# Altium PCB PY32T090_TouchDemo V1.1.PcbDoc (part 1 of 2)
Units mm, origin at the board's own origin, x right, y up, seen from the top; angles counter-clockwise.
Board outline 86.5 x 140.97 mm, 2 copper layers (Top Layer, Bottom Layer); 152 components, 143 nets, 461 pads, 174 vias.
Unrouted connection lines stored in the file: 2.
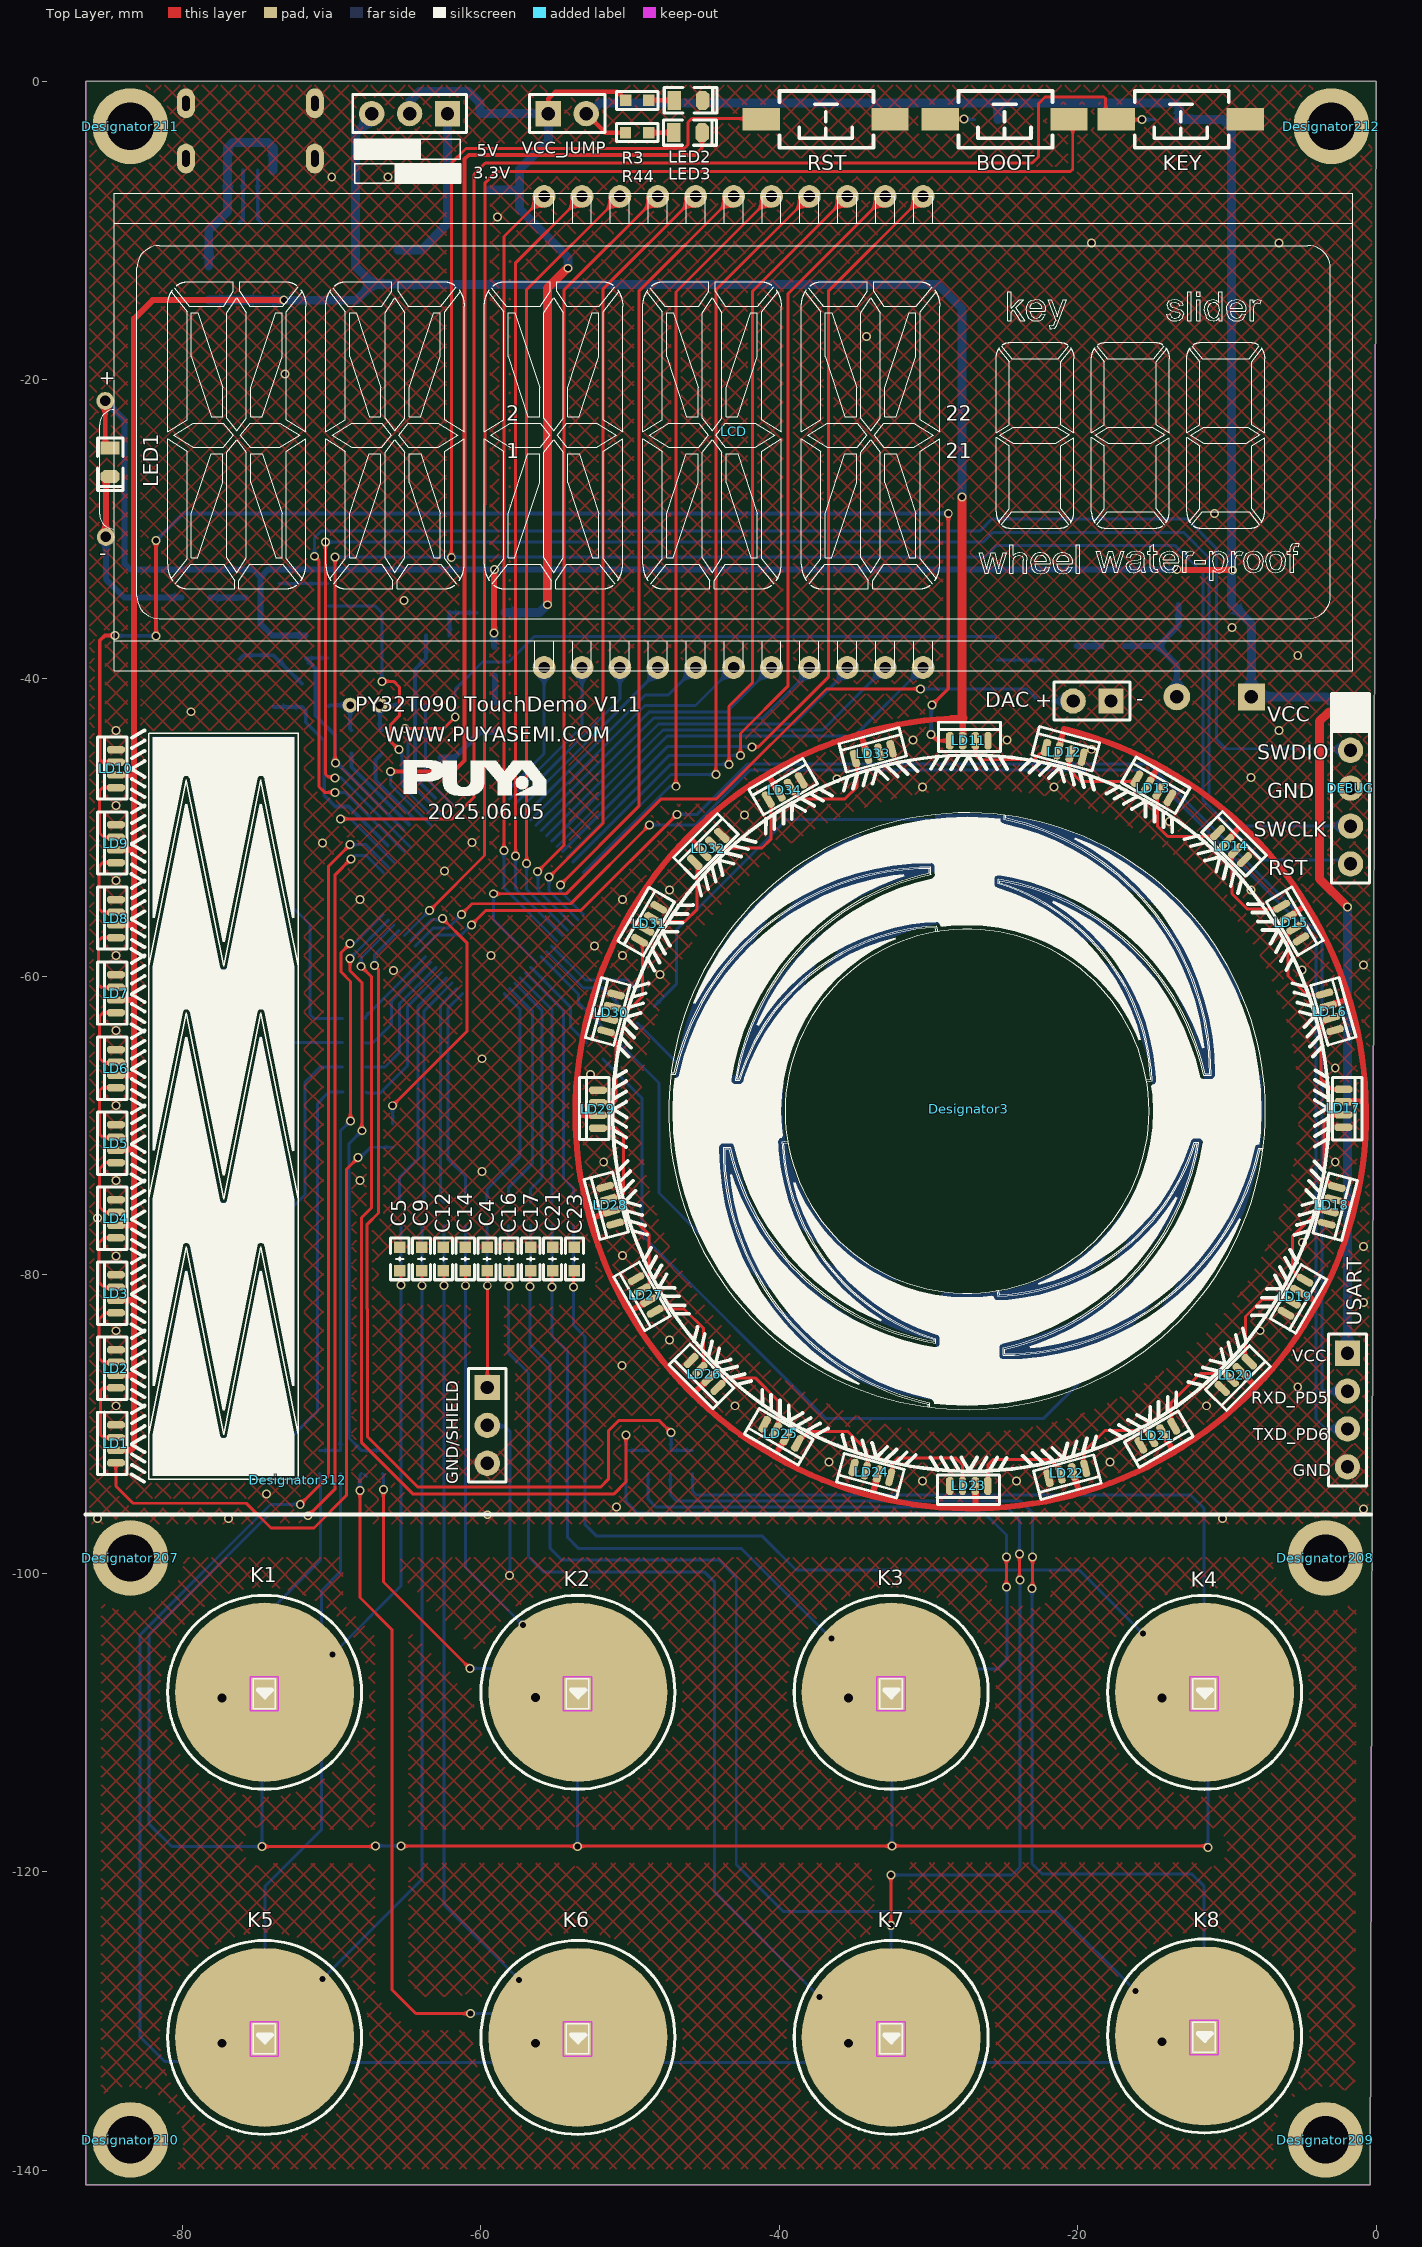
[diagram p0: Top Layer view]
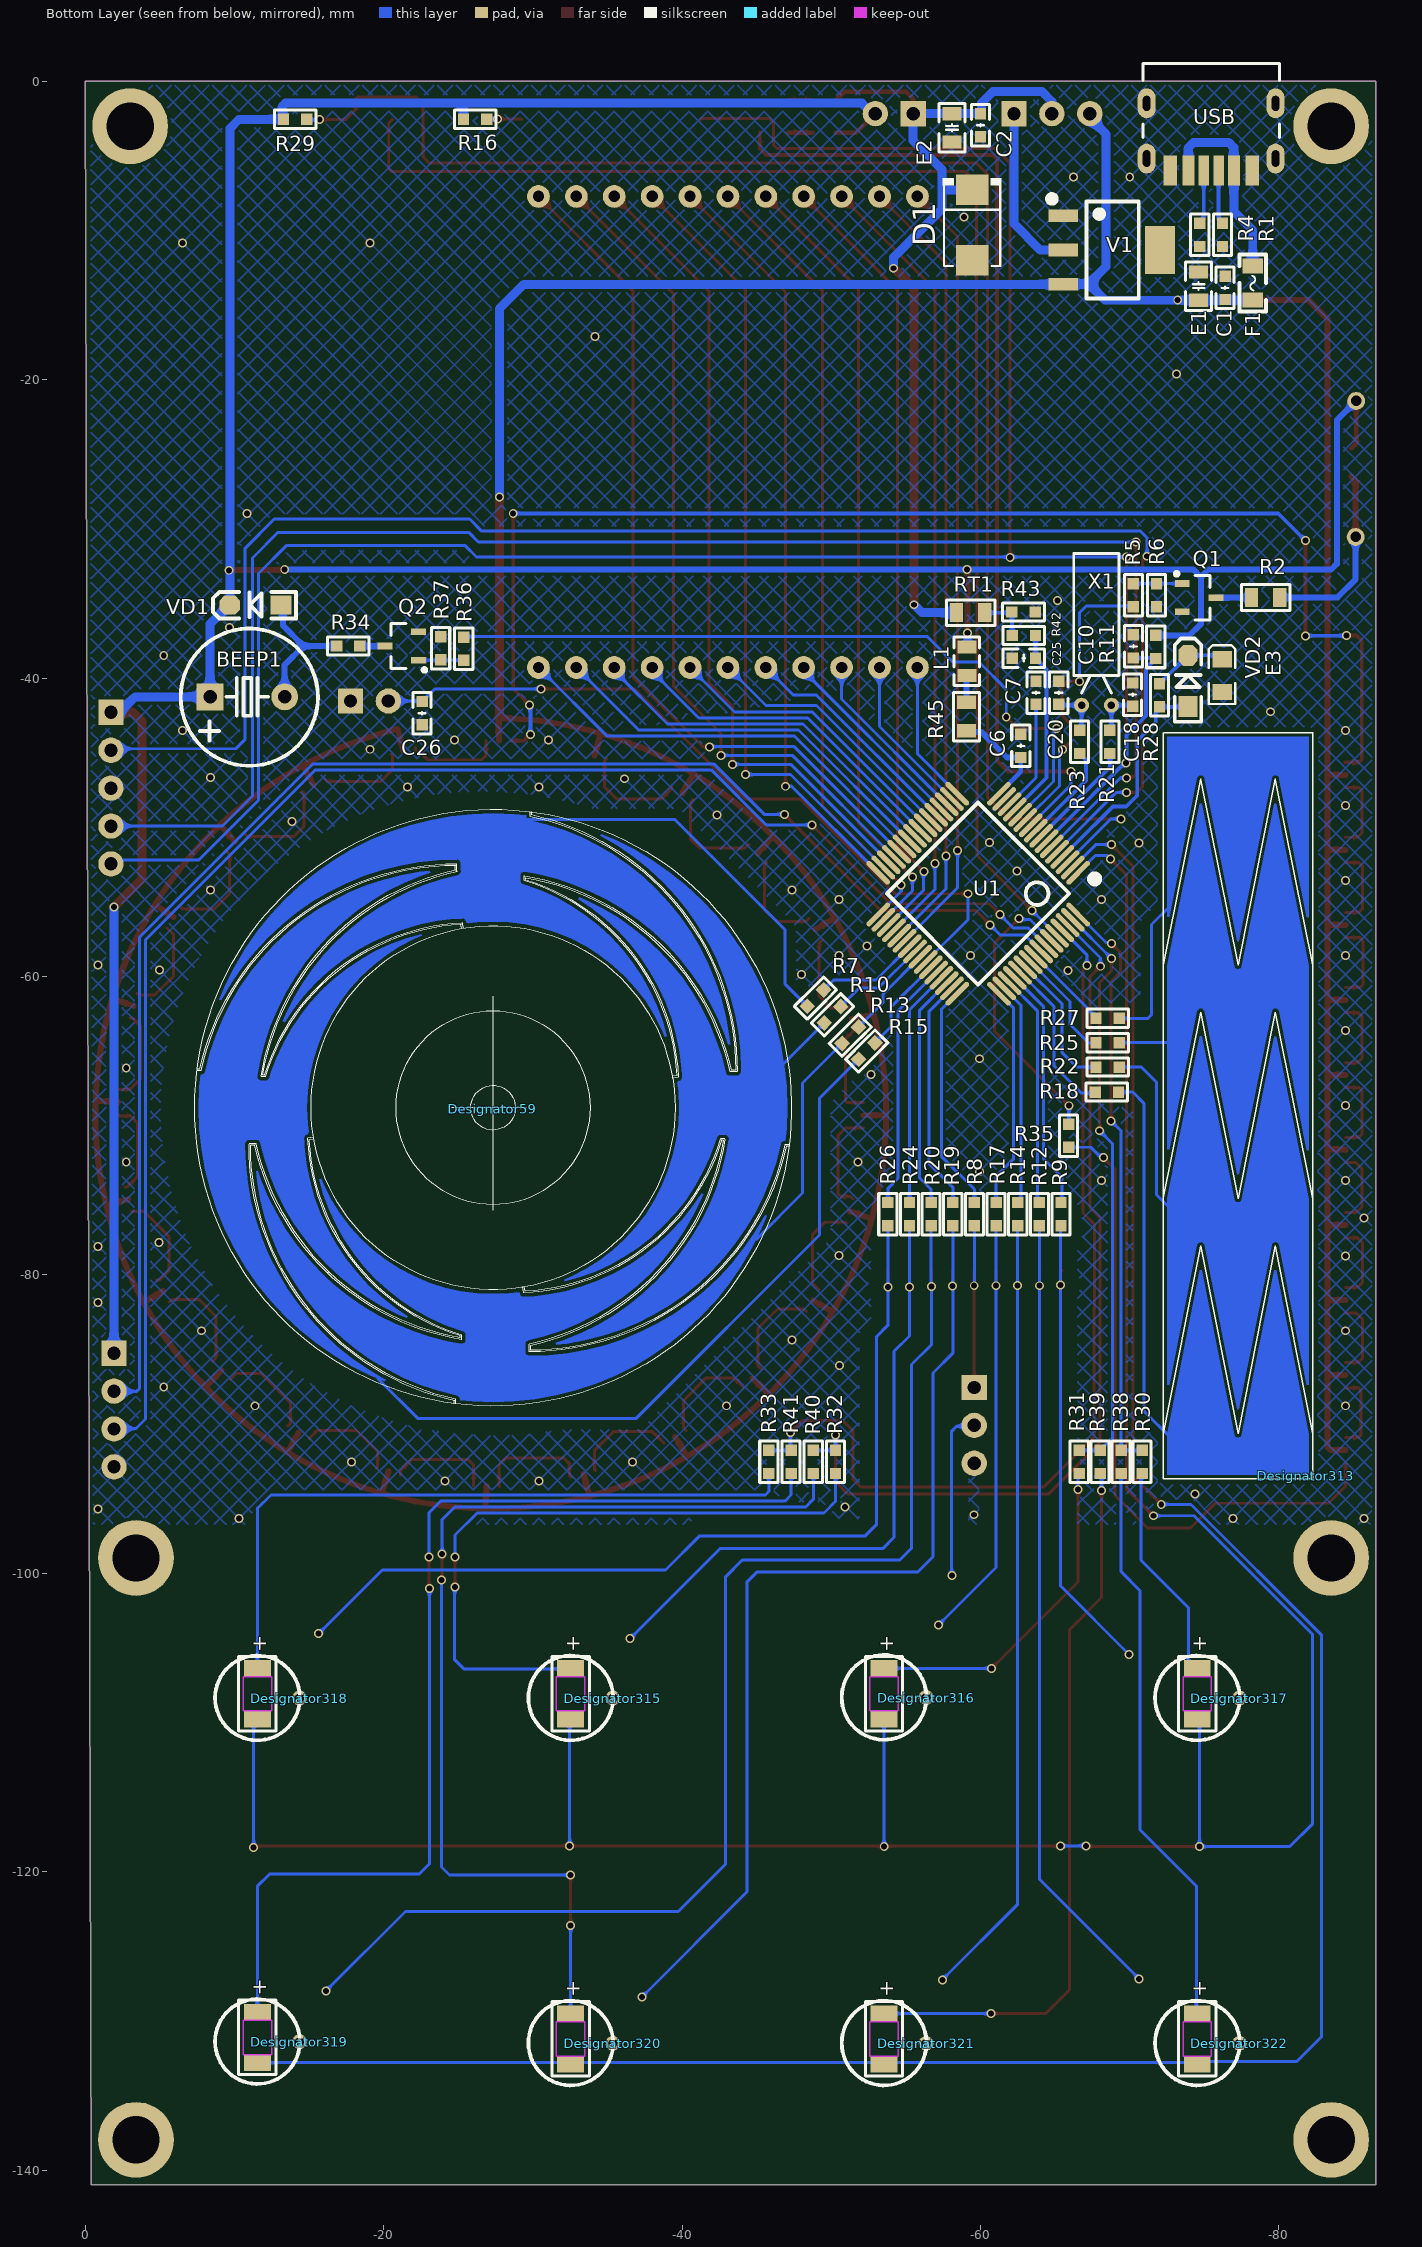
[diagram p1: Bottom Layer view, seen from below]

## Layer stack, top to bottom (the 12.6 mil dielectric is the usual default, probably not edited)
Top Solder: solder mask 0.0102, Solder Resist, Dk 3.5
Top Layer: signal copper 0.0356
Dielectric 1: dielectric 0.32, FR-4, Dk 4.8
Bottom Layer: signal copper 0.0356
Bottom Solder: solder mask 0.0102, Solder Resist, Dk 3.5

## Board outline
-86.5,-140.97 -86.5,0 0,0 -0.394,-140.97

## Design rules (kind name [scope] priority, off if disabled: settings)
Clearance Clearance_17 [All vs InNet('NetC3_2')] p1: gap=0.6 ignorepadtopadclearanceinfootprint=FALSE
Clearance Clearance_16 [All vs InNet('NetC8_2')] p2: gap=0.6 ignorepadtopadclearanceinfootprint=FALSE
Clearance Clearance_15 [All vs InNet('NetC11_2')] p3: gap=0.6 ignorepadtopadclearanceinfootprint=FALSE
Clearance Clearance_14 [All vs InNet('NetC13_2')] p4: gap=0.6 ignorepadtopadclearanceinfootprint=FALSE
Clearance Clearance_13 [All vs InNet('NetC24_2')] p5: gap=0.6 ignorepadtopadclearanceinfootprint=FALSE
Clearance Clearance_12 [All vs InNet('NetC22_2')] p6: gap=0.6 ignorepadtopadclearanceinfootprint=FALSE
Clearance Clearance_11 [All vs InNet('NetC19_2')] p7: gap=0.6 ignorepadtopadclearanceinfootprint=FALSE
Clearance Clearance_10 [All vs InNet('NetC15_2')] p8: gap=0.6 ignorepadtopadclearanceinfootprint=FALSE
Clearance Clearance_9 [All vs InNet('shield_pad')] p9: gap=1 ignorepadtopadclearanceinfootprint=FALSE
Clearance Clearance_18 [All vs InNet('NetC4_2')] p10: gap=1 ignorepadtopadclearanceinfootprint=FALSE
Clearance [All vs InNet('NetC5_2')] p11: gap=1 ignorepadtopadclearanceinfootprint=FALSE
Clearance Clearance_8 [All vs InNet('NetC17_2')] p12: gap=1 ignorepadtopadclearanceinfootprint=FALSE
Clearance Clearance_7 [All vs InNet('NetC14_2')] p13: gap=1 ignorepadtopadclearanceinfootprint=FALSE
Clearance Clearance_6 [All vs InNet('NetC9_2')] p14: gap=1 ignorepadtopadclearanceinfootprint=FALSE
Clearance Clearance_5 [All vs InNet('NetC12_2')] p15: gap=1 ignorepadtopadclearanceinfootprint=FALSE
Clearance Clearance_4 [All vs InNet('NetC21_2')] p16: gap=1 ignorepadtopadclearanceinfootprint=FALSE
Clearance Clearance_3 [All vs InNet('NetC16_2')] p17: gap=1 ignorepadtopadclearanceinfootprint=FALSE
Clearance Clearance_2 [All vs InNet('NetC23_2')] p18: gap=1 ignorepadtopadclearanceinfootprint=FALSE
Clearance Clearance_1 [All] p19: gap=0.2 ignorepadtopadclearanceinfootprint=FALSE
PlaneConnect [All] p1: planeconnectstyle=Direct reliefexpansion=0.508 reliefentries=4 reliefconductorwidth=0.254 reliefairgap=0.254
PolygonConnect [All] p1: connectstyle=Direct reliefconductorwidth=0.254 reliefentries=4 polygonreliefangle="90 Angle" airgapwidth=0.254
RoutingVias [All] p1: holewidth=0.711 width=1.27 viastyle="Through Hole" minholewidth=0.711 minwidth=1.27 maxholewidth=0.711 maxwidth=1.27
SolderMaskExpansion [All] p1: expansion=0.102 istentingtop=FALSE
Width [All] p1: maxlimit=1 minlimit=0.2 preferedwidth=0.254
29 further rules are at their usual default settings.

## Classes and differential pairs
component class PY32T092_TK_TEST: 5V BOOT C1 C2 C4 C5 C6 C7 C9 C10 C12 C14 C16 C17 C18 C20 C21 C23 C25 C26 DAC DEBUG E1 E2 E3 F1 K1 K2 K3 K4 K5 K6 K7 K8 KEY LCD LED1 LED2 LED3 Q1 R1 R2 R3 R4 R5 R6 R7 R8 R9 R10 R11 R12 R13 R14 R15 R16 R17 R18 R19 R20 R21 R22 R23 R24 R25 R26 R27 R28 R29 R42 R43 R44 RST RT1 U1 USART USB V1 VCC_JUMP VD2 X1
component class "PY32T092_Demo LED": BEEP1 LD1 LD2 LD3 LD4 LD5 LD6 LD7 LD8 LD9 LD10 LD11 LD12 LD13 LD14 LD15 LD16 LD17 LD18 LD19 LD20 LD21 LD22 LD23 LD24 LD25 LD26 LD27 LD28 LD29 LD30 LD31 LD32 LD33 LD34 Q2 R30 R31 R32 R33 R34 R35 R36 R37 R38 R39 R40 R41 VD1

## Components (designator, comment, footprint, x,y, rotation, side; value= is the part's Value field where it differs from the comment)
5V "HDR-1X3" HDR2.54-LI-3P -64.783,-2.159 r180 top (schematic designator JUMP)
BEEP1 "DC5V" "BEEP 5x9x5.5" -10.859,-41.25 r270 bottom
BOOT "6x6x5" "TSW SMD-3*6*5" -24.905,-2.54 r180 top
C1 "104" "C 0603_L" -76.391,-13.843 r270 bottom
C2 "104" "C 0603_L" -59.995,-2.936 r90 bottom
C4 "5pf" "C 0603_L" -59.589,-78.928 r270 top
C5 "5pf" "C 0603_L" -65.443,-78.928 r270 top
C6 "104" "C 0603_L" -62.7,-44.539 r270 bottom
C7 "2.2NF" "C 0603_L" -63.716,-40.97 r270 bottom
C9 "5pf" "C 0603_L" -63.98,-78.928 r270 top
C10 "104" "C 0603_L" -70.244,-37.871 r270 bottom
C12 "5pf" "C 0603_L" -62.516,-78.928 r270 top
C14 "5pf" "C 0603_L" -61.052,-78.928 r270 top
C16 "5pf" "C 0603_L" -58.125,-78.928 r270 top
C17 "5pf" "C 0603_L" -56.661,-78.928 r270 top
C18 "20PF" "C 0603_L" -70.193,-41.097 r270 bottom
C20 "20PF" "C 0603_L" -65.24,-40.97 r90 bottom
C21 "5pf" "C 0603_L" -55.198,-78.928 r270 top
C23 "5pf" "C 0603_L" -53.734,-78.928 r270 top
C25 "104" "C 0603_L" -62.903,-38.659 r180 bottom
C26 "104" "C 0603_L" -22.568,-42.342 r90 bottom
D1 "SMBJ5.0A" SMB_L4.6-W3.6-LS5.3-RD -59.436,-9.625 r270 bottom
DAC "HDR-1X2" HDR2.54-LI-2P -19.038,-41.529 r180 top (schematic designator DAC_OUT)
DEBUG "ISP" ISP_DIP_2.54_5P -1.715,-42.291 r270 top
Designator3 "Comment" "circular ring_top" -27.293,-68.859 r0 top locked
Designator59 "Comment" PAD_Wheel -27.293,-68.859 r90 bottom locked
Designator207 "Comment" "M3 125X200"#1 -78.5,-102.759 r0 top
Designator208 "Comment" "M3 125X200"#2 1.027,-103.318 r0 top
Designator209 "Comment" "M3 125X200"#3 1.129,-140.554 r0 top
Designator210 "Comment" "M3 125X200"#4 -78.78,-140.173 r0 top
Designator211 "Comment" "M3 125X200"#5 -79.008,-6.01 r0 top
Designator212 "Comment" "M3 125X200"#6 1.002,-6.01 r0 top
Designator312 "Comment" T092_WHEEL_TOP -72.276,-93.726 r90 top
Designator313 "Comment" T092_Wheel -81.801,-93.472 r90 bottom
Designator315 "Comment" TP -32.523,-108.347 r180 bottom
Designator316 "Comment" TP -53.524,-108.309 r180 bottom
Designator317 "Comment" TP -74.523,-108.347 r180 bottom
Designator318 "Comment" TP -11.523,-108.347 r180 bottom
Designator319 "Comment" TP -11.523,-131.377 r180 bottom
Designator320 "Comment" TP -32.523,-131.478 r180 bottom
Designator321 "Comment" TP -53.523,-131.478 r180 bottom
Designator322 "Comment" TP -74.523,-131.478 r180 bottom
E1 "10uF/10V" "C 0805_L" -74.613,-13.716 r90 bottom
E2 "10uF/10V" "C 0805_L" -58.09,-3.109 r270 bottom
E3 "220uF/10V" "CD S(2012)" -76.188,-39.827 r270 bottom
F1 "500ma" "FU 0805" -78.245,-13.513 r270 bottom
GND/SHIELD "HDR-1X3" HDR2.54-LI-3P -59.576,-90.081 r270 top
K1 "Comment" T-LED -74.5,-107.97 r90 top (schematic designator K0)
K2 "Comment" T-LED -53.5,-107.97 r90 top (schematic designator K5)
K3 "Comment" T-LED -32.5,-107.97 r90 top (schematic designator K6)
K4 "Comment" T-LED -11.5,-107.97 r90 top (schematic designator K2)
K5 "Comment" T-LED -74.5,-131.101 r90 top (schematic designator K7)
K6 "Comment" T-LED -53.5,-131.101 r90 top (schematic designator K8)
K7 "Comment" T-LED -32.5,-131.101 r90 top (schematic designator K3)
K8 "Comment" T-LED -11.5,-131 r90 top (schematic designator K4)
KEY "6x6x5" "TSW SMD-3*6*5" -13.094,-2.54 r180 top (schematic designator KEY1)
L1 "1uH" "L 0805_L" -59.08,-38.862 r90 bottom
LCD "PY_LCD" PY-LCD -43.066,-23.495 r0 top locked
LD1 "LED1" LED_WS -84.489,-91.298 r90 top
LD2 "LED1" LED_WS -84.489,-86.269 r90 top
LD3 "LED1" LED_WS -84.489,-81.24 r90 top
LD4 "LED1" LED_WS -84.489,-76.211 r90 top
LD5 "LED1" LED_WS -84.489,-71.182 r90 top
LD6 "LED1" LED_WS -84.489,-66.153 r90 top
LD7 "LED1" LED_WS -84.489,-61.124 r90 top
LD8 "LED1" LED_WS -84.489,-56.095 r90 top
LD9 "LED1" LED_WS -84.489,-51.066 r90 top
LD10 "LED1" LED_WS -84.489,-46.037 r90 top
LD11 "LED1" LED_WS -27.267,-44.171 r0 top
LD12 "LED1" LED_WS -20.866,-44.958 r345 top
LD13 "LED1" LED_WS -14.897,-47.371 r330 top
LD14 "LED1" LED_WS -9.69,-51.257 r315.12 top
LD15 "LED1" LED_WS -5.652,-56.388 r300.49 top
LD16 "LED1" LED_WS -3.086,-62.382 r286 top
LD17 "LED1" LED_WS -2.176,-68.849 r270 top
LD18 "LED1" LED_WS -2.959,-75.362 r255 top
LD19 "LED1" LED_WS -5.398,-81.483 r240 top
LD20 "LED1" LED_WS -9.411,-86.741 r225 top
LD21 "LED1" LED_WS -14.669,-90.805 r210 top
LD22 "LED1" LED_WS -20.739,-93.32 r195 top
LD23 "LED1" LED_WS -27.318,-94.158 r180 top
LD24 "LED1" LED_WS -33.82,-93.243 r165 top
LD25 "LED1" LED_WS -39.916,-90.653 r150 top
LD26 "LED1" LED_WS -45.047,-86.639 r135 top
LD27 "LED1" LED_WS -48.996,-81.337 r120 top
LD28 "LED1" LED_WS -51.372,-75.311 r105 top
LD29 "LED1" LED_WS -52.185,-68.859 r90 top
LD30 "LED1" LED_WS -51.296,-62.408 r75 top
LD31 "LED1" LED_WS -48.73,-56.439 r60 top
LD32 "LED1" LED_WS -44.768,-51.41 r45 top
LD33 "LED1" LED_WS -33.693,-45.034 r15 top
LD34 "LED1" LED_WS -39.637,-47.473 r30 top
LED1 "白色" "LED 0805G" -84.849,-25.527 r270 top
LED2 "红色" "LED 0805W" -46.089,-1.27 r0 top
LED3 "红色" "LED 0805W" -46.124,-3.429 r0 top
Q1 "SS8050" SOT23-3L -74.664,-34.605 r270 bottom
Q2 "SS8050" SOT23-3L -21.197,-37.846 r90 bottom
R1 "5.1K" "R 0603_L" -76.213,-10.287 r90 bottom
R2 "10R" "R 0805_L" -79.109,-34.595 r180 bottom
R3 "1K" "R 0603_L" -49.518,-1.27 r180 top
R4 "5.1K" "R 0603_L" -74.689,-10.287 r90 bottom
R5 "1K" "R 0603_L" -70.244,-34.442 r270 bottom
R6 "10K" "R 0603_L" -71.793,-34.442 r90 bottom
R7 "4.3K" "R 0603_L" -48.933,-61.443 r315 bottom
R8 "4.3K" "R 0603_L" -59.589,-75.921 r270 bottom
R9 "4.3K" "R 0603_L" -65.393,-75.921 r270 bottom
R10 "4.3K" "R 0603_L" -50.076,-62.56 r315 bottom
R11 "10K" "R 0603_L" -71.743,-37.907 r90 bottom
R12 "4.3K" "R 0603_L" -63.942,-75.921 r270 bottom
R13 "4.3K" "R 0603_L" -51.27,-63.932 r315 bottom
R14 "4.3K" "R 0603_L" -62.491,-75.921 r270 bottom
R15 "4.3K" "R 0603_L" -52.372,-64.989 r315 bottom
R16 "1K" "R 0603_L" -26.124,-2.54 r0 bottom value=10K
R17 "4.3K" "R 0603_L" -61.04,-75.921 r270 bottom
R18 "4.3K" "R 0603_L" -68.466,-67.742 r180 bottom
R19 "4.3K" "R 0603_L" -58.138,-75.921 r270 bottom
R20 "4.3K" "R 0603_L" -56.687,-75.921 r270 bottom
R21 "0R" "R 0603_L" -68.669,-44.272 r90 bottom
R22 "4.3K" "R 0603_L" -68.517,-66.065 r180 bottom
R23 "0R" "R 0603_L" -66.637,-44.272 r90 bottom
R24 "4.3K" "R 0603_L" -55.236,-75.921 r270 bottom
R25 "4.3K" "R 0603_L" -68.517,-64.431 r180 bottom
R26 "4.3K" "R 0603_L" -53.785,-75.921 r270 bottom
R27 "4.3K" "R 0603_L" -68.517,-62.797 r180 bottom
R28 "1M" "R 0603_L" -71.997,-41.148 r90 bottom value=10K
R29 "10K" "R 0603_L" -14.059,-2.54 r0 bottom
R30 "510R" "R 0603_L" -70.828,-92.532 r270 bottom
R31 "510R" "R 0603_L" -66.612,-92.532 r270 bottom
R32 "510R" "R 0603_L" -50.28,-92.532 r270 bottom
R33 "510R" "R 0603_L" -45.809,-92.532 r270 bottom
R34 "200R" "R 0603_L" -17.615,-37.846 r0 bottom
R35 "510R" "R 0603_L" -65.901,-70.663 r270 bottom
R36 "1K" "R 0603_L" -25.362,-38.024 r90 bottom
R37 "10K" "R 0603_L" -23.813,-37.998 r270 bottom
R38 "510R" "R 0603_L" -69.423,-92.532 r270 bottom
R39 "510R" "R 0603_L" -68.017,-92.532 r270 bottom
R40 "510R" "R 0603_L" -48.789,-92.532 r270 bottom
R41 "510R" "R 0603_L" -47.299,-92.532 r270 bottom
R42 "1K" "R 0603_L" -62.903,-37.135 r180 bottom
R43 "10K" "R 0603_L" -62.878,-35.56 r180 bottom
R44 "1K" "R 0603_L" -49.533,-3.429 r180 top
R45 "10Ω" "R 0805_L" -59.055,-42.57 r270 bottom
RST "6x6x5" "TSW SMD-3*6*5" -36.894,-2.54 r180 top (schematic designator RST1)
RT1 "10K" "R 0805_L" -59.337,-35.611 r180 bottom
U1 "PY32T092" "LQFP64 10x10_M" -59.836,-54.441 r45 bottom
USART "ISP" HDR2.54-Y-LI-4P -1.918,-89.052 r270 top
USB "USB-C" USB-C/S_C -75.455,1.081 r0 bottom (schematic designator USB_POWER1)
V1 "AMS1117-3V3" SOT223_N -68.847,-11.303 r270 bottom
VCC_JUMP "HDR-1X2" HDR2.54-LI-2P -54.217,-2.159 r0 top (schematic designator VCC_JUMP1)
VD1 "A7" SOD-123 -11.392,-35.103 r0 bottom
VD2 "A7" SOD-123 -73.902,-40.183 r90 bottom
X1 "32.768KHZ" OSC-3x8-WI-A -67.771,-41.808 r180 bottom

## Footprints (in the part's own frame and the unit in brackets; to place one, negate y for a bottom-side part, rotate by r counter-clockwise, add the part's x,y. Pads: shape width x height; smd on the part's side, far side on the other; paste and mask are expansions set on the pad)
"BEEP 5x9x5.5" [mm] "5*9*5.5mm(脚距,直径,高度)"
  rect 1.8x1.8 hole 0.9: 1(0,-2.5)
  round 1.8 hole 0.9: 2(0,2.5)
  silkscreen extent -4.57,-4.47 4.62,4.73, body extent -4.5,-4.5 4.5,4.5, height 5.45
"C 0603_L" [mil] "无极性贴片电容"
  rect 30x30 smd: 1(-30.59,0) 2(30.59,0)
  silkscreen extent -55,-24 55,24, body extent -31,-16 31,16, height 32
"C 0805_L" [mil] "无极性贴片电容"
  rect 35x50 smd: 1(-37.4,0) 2(37.4,0)
  silkscreen extent -64,-34 64,34, body extent -39,-24 39,24, height 20
"CD S(2012)" [mm] "长2.0mm，宽1.25mm，厚1.2mm"
  rect 1.1x1.3 smd: 1(-1.1,0) 2(1.1,0)
  silkscreen extent -2.03,-0.89 1.91,0.89, body extent -1,-0.6 1,0.6, height 1.2
"circular ring_top" [mm]
  silkscreen extent -20.12,-20.16 19.87,19.84
"FU 0805" [mil] "贴片保险丝"
  rect 40x55 smd: 1(-45,0) 2(45,0)
  silkscreen extent -75,-35 75,35, body extent -39,-24 39,24, height 20
HDR2.54-LI-2P [mm] "排针，2脚"
  rect 1.7x1.7 hole 0.9: 1(-1.27,0)
  round 1.7 hole 0.9: 2(1.27,0)
  silkscreen extent -2.54,-1.27 2.54,1.27, body extent -2.54,-1.27 2.54,1.27, height 8.5
HDR2.54-LI-3P [mm] "排针，3脚"
  rect 1.7x1.7 hole 0.9: 1(-2.54,0)
  round 1.7 hole 0.9: 2(0,0) 3(2.54,0)
  silkscreen extent -3.81,-1.27 3.81,1.27, body extent -3.81,-1.27 3.81,1.27, height 8.5
HDR2.54-Y-LI-4P [mm] "圆孔排母，4脚"
  rect 1.7x1.7 hole 0.9: 1(-3.81,0)
  round 1.7 hole 0.9: 2(-1.27,0) 3(1.27,0) 4(3.81,0)
  silkscreen extent -5.08,-1.27 5.08,1.27, body extent -5.08,-1.27 5.08,1.27, height 4.31
ISP_DIP_2.54_5P [mm] "5P 下载端口"
  rect 1.7x1.7 hole 0.9: 1(0,0)
  round 1.7 hole 0.9: 2(2.54,0) 3(5.08,0) 4(7.62,0) 5(10.16,0)
  silkscreen extent -1.27,-1.27 11.43,1.27
"L 0805_L" [mil] "小功率贴片电感"
  rect 35x50 smd: 1(-37.4,0) 2(37.4,0)
  silkscreen extent -64,-34 64,34, body extent -39,-24 39,24, height 35
"LED 0805G" [mil] "绿色0805LED"
  rect 35x50 smd: 1(-37.4,0)
  oct 35x50 smd: 2(37.4,0)
  silkscreen extent -64,-33 75,33, body extent -39,-25 39,25, height 32
"LED 0805W" [mm] "白色0805LED"
  rect 0.889x1.27 smd: 1(-0.95,0)
  oct 0.889x1.27 smd: 2(0.95,0)
  silkscreen extent -1.62,-0.85 1.9,0.85, body extent -1,-0.63 1,0.63, height 0.8
LED_WS [mm]
  oct 0.5x1.2 smd: 1(-1.295,-0.021) 2(-0.445,-0.021) 3(0.405,-0.021) 4(1.255,-0.021)
  silkscreen extent -2.57,-1.94 2.54,1.22
"LQFP64 10x10_M" [mm] "64脚，体宽10x10mm，脚距0.5mm"
  oval 0.35x2.1 smd: 1(-3.75,-5.727) 2(-3.25,-5.727) 3(-2.75,-5.727) 4(-2.25,-5.727) 5(-1.75,-5.727) 6(-1.25,-5.727) 7(-0.75,-5.727) 8(-0.25,-5.727) 9(0.25,-5.727) 10(0.75,-5.727) 11(1.25,-5.727) 12(1.75,-5.727) 13(2.25,-5.727) 14(2.75,-5.727) 15(3.25,-5.727) 16(3.75,-5.727) 33(3.75,5.727) 34(3.25,5.727) 35(2.75,5.727) 36(2.25,5.727) 37(1.75,5.727) 38(1.25,5.727) 39(0.75,5.727) 40(0.25,5.727) 41(-0.25,5.727) 42(-0.75,5.727) 43(-1.25,5.727) 44(-1.75,5.727) 45(-2.25,5.727) 46(-2.75,5.727) 47(-3.25,5.727) 48(-3.75,5.727)
  oval 2.1x0.35 smd: 17(5.727,-3.75) 18(5.727,-3.25) 19(5.727,-2.75) 20(5.727,-2.25) 21(5.727,-1.75) 22(5.727,-1.25) 23(5.727,-0.75) 24(5.727,-0.25) 25(5.727,0.25) 26(5.727,0.75) 27(5.727,1.25) 28(5.727,1.75) 29(5.727,2.25) 30(5.727,2.75) 31(5.727,3.25) 32(5.727,3.75) 49(-5.727,3.75) 50(-5.727,3.25) 51(-5.727,2.75) 52(-5.727,2.25) 53(-5.727,1.75) 54(-5.727,1.25) 55(-5.727,0.75) 56(-5.727,0.25) 57(-5.727,-0.25) 58(-5.727,-0.75) 59(-5.727,-1.25) 60(-5.727,-1.75) 61(-5.727,-2.25) 62(-5.727,-2.75) 63(-5.727,-3.25) 64(-5.727,-3.75)
  silkscreen extent -5.08,-6.47 4.32,4.32, body extent -6,-6 6,6, height 1.45
"M3 125X200"#1 [mm] "M3螺丝孔，孔125Mil，焊盘200Mil"
  round 5.08 hole 3.175: 1(-5,3.789)
"M3 125X200"#2 [mm] "M3螺丝孔，孔125Mil，焊盘200Mil"
  round 5.08 hole 3.175: 1(-4.421,4.348)
"M3 125X200"#3 [mm] "M3螺丝孔，孔125Mil，焊盘200Mil"
  round 5.08 hole 3.175: 1(-4.523,2.584)
"M3 125X200"#4 [mm] "M3螺丝孔，孔125Mil，焊盘200Mil"
  round 5.08 hole 3.175: 1(-4.72,2.203)
"M3 125X200"#5 [mm] "M3螺丝孔，孔125Mil，焊盘200Mil"
  round 5.08 hole 3.175: 1(-4.492,3.01)
"M3 125X200"#6 [mm] "M3螺丝孔，孔125Mil，焊盘200Mil"
  round 5.08 hole 3.175: 1(-4.002,3.01)
OSC-3x8-WI-A [mm] "脚距：2mm"
  round 1 hole 0.5: 1(1,0) 2(-1,0)
  silkscreen extent -1.52,0.8 1.52,10.16, body extent -1.5,-0.18 1.5,10, height 3.03
PAD_Wheel [mm]
  Top Layer region: 178 vertices and 0 holes, not listed, extent 4.285,-15.918 19.803,18.314
  Top Layer region: 178 vertices and 0 holes, not listed, extent -15.818,-19.764 18.414,-4.247
  Top Layer region: 178 vertices and 0 holes, not listed, extent -18.275,4.184 15.957,19.702
  Top Layer region: 181 vertices and 0 holes, not listed, extent -19.664,-18.376 -4.146,15.856
  silkscreen extent -19.93,-20.03 20.07,19.97
PY-LCD [mil]
  round 60 hole 30: 1(-500,-621.63) 2(-400,-621.63) 3(-300,-621.63) 4(-200,-621.63) 5(-100,-621.63) 6(0,-621.63) 7(100,-621.63) 8(200,-621.63) 9(300,-621.63) 10(400,-621.63) 11(500,-621.63) 12(500,621.63) 13(400,621.63) 14(300,621.63) 15(200,621.63) 16(100,621.63) 17(0,621.63) 18(-100,621.63) 19(-200,621.63) 20(-300,621.63) 21(-400,621.63) 22(-500,621.63)
  silkscreen extent -1673,-630 1634,630
"R 0603_L" [mil] "1/10W贴片电阻"
  rect 30x30 smd: 1(-30.59,0) 2(30.59,0)
  silkscreen extent -55,-24 55,24, body extent -31,-16 31,16, height 16
"R 0805_L" [mil] "1/8W贴片电阻"
  rect 35x50 smd: 1(-37.4,0) 2(37.4,0)
  silkscreen extent -64,-34 64,34, body extent -39,-25 39,25, height 20
SMB_L4.6-W3.6-LS5.3-RD [mm]
  rect 2.047x2.192 smd: 1(-2.361,0) 2(2.361,0)
  silkscreen extent -3.12,-1.96 2.74,1.96
SOD-123 [mil] "2.7x1.6X1.1mm（长宽高，不包括引脚）"
  rect 55x50 smd: 1(-67.5,0)
  oct 55x50 smd: 2(67.5,0)
  silkscreen extent -108,-35 112,35, body extent -73,-31 73,31, height 48
SOT23-3L [mm] "3x1.3x1mm(长宽高)"
  rect 0.45x1 smd: 1(-0.95,-1.143) 2(0.95,-1.143) 3(0,1.125)
  silkscreen extent -1.72,-1.65 1.5,0.7, body extent -1.5,-1.2 1.5,1.2, height 1.05
SOT223_N [mm] "6.4x7x1.6mm(长宽高)"
  rect 0.85x2 smd: 1(-2.3,-3.302) 2(0,-3.302) 3(2.3,-3.302)
  rect 3.2x2 smd: 2(0,3.175)
  silkscreen extent -3.63,-4.26 3.25,1.75, body extent -3.25,-3.51 3.25,3.51, height 1.65
T092_Wheel [mm]
  Top Layer region: 49.564,-0.199 37.458,-0.199 37.445,-0.073 46.711,1.79 46.773,1.79 46.867,1.828 46.938,1.899 46.977,1.992 46.977,2.093 46.938,2.186 46.867,2.257 46.774,2.296 35.852,4.48 35.852,4.607 46.711,6.79 46.773,6.79 46.867,6.828 46.938,6.899 46.977,6.992 46.977,7.093 46.938,7.186 46.867,7.257 46.774,7.296 37.462,9.158 37.474,9.285 49.564,9.285
  Top Layer region: 45.062,7.112 45.062,6.985 34.171,4.796 34.125,4.777 34.079,4.758 34.079,4.757 34.078,4.757 34.043,4.722 34.008,4.686 34.008,4.686 34.007,4.686 33.988,4.64 33.969,4.593 33.969,4.593 33.969,4.593 33.969,4.543 33.969,4.493 33.969,4.492 33.969,4.492 33.988,4.446 34.007,4.4 34.008,4.399 34.008,4.399 34.043,4.364 34.079,4.328 34.079,4.328 34.079,4.328 34.125,4.309 34.172,4.29 45.062,2.112 45.062,1.985 34.197,-0.199 21.838,-0.199 21.826,-0.073 31.137,1.79 31.137,1.79 31.23,1.828 31.302,1.899 31.34,1.992 31.34,2.093 31.302,2.186 31.231,2.257 31.138,2.296 20.221,4.479 20.221,4.606 31.137,6.789 31.137,6.789 31.137,6.79 31.137,6.79 31.139,6.79 31.23,6.828 31.302,6.899 31.34,6.992 31.341,7.093 31.302,7.186 31.231,7.257 31.23,7.258 31.23,7.258 31.229,7.258 31.138,7.296 21.873,9.158 21.886,9.285 34.197,9.285
  Top Layer region: 29.457,7.107 29.457,6.98 18.536,4.796 18.443,4.757 18.372,4.686 18.334,4.593 18.334,4.492 18.372,4.399 18.444,4.328 18.537,4.29 18.537,4.29 29.453,2.106 29.453,1.979 18.561,-0.199 6.099,-0.199 6.087,-0.073 15.472,1.79 15.473,1.79 15.473,1.79 15.519,1.809 15.566,1.828 15.566,1.828 15.566,1.828 15.601,1.863 15.637,1.899 15.637,1.899 15.637,1.899 15.656,1.946 15.675,1.992 15.675,1.992 15.675,1.993 15.675,2.043 15.675,2.093 15.675,2.093 15.675,2.093 15.656,2.14 15.637,2.186 15.637,2.186 15.637,2.186 15.601,2.222 15.566,2.257 15.566,2.257 15.566,2.258 15.519,2.277 15.473,2.296 15.473,2.296 15.472,2.296 4.469,4.479 4.469,4.606 15.472,6.79 15.473,6.79 15.473,6.79 15.519,6.809 15.566,6.828 15.566,6.828 15.566,6.828 15.601,6.863 15.637,6.899 15.637,6.899 15.637,6.899 15.656,6.946 15.675,6.992 15.675,6.992 15.675,6.993 15.675,7.043 15.675,7.093 15.675,7.093 15.675,7.093 15.656,7.14 15.637,7.186 15.637,7.186 15.637,7.186 15.601,7.222 15.566,7.257 15.566,7.257 15.566,7.258 15.519,7.277 15.473,7.296 15.473,7.296 15.472,7.296 6.087,9.158 6.099,9.285 18.624,9.285
  Top Layer region: 13.776,7.106 13.776,6.979 2.772,4.796 2.772,4.796 2.772,4.796 2.726,4.777 2.679,4.758 2.679,4.757 2.679,4.757 2.643,4.722 2.608,4.686 2.608,4.686 2.607,4.686 2.588,4.639 2.569,4.593 2.569,4.593 2.569,4.593 2.569,4.543 2.569,4.493 2.569,4.492 2.569,4.492 2.588,4.447 2.607,4.399 2.608,4.399 2.608,4.399 2.643,4.364 2.679,4.328 2.679,4.328 2.679,4.328 2.726,4.309 2.772,4.29 2.772,4.29 2.772,4.29 13.776,2.106 13.776,1.979 2.797,-0.199 0.08,-0.199 0.08,9.285 2.797,9.285
  silkscreen extent -0.18,-0.48 49.82,9.54
T092_WHEEL_TOP [mm]
  silkscreen extent 0.03,-0.05 50.03,9.97
T-LED [mm]
  rect 1.1x1.8 smd far side: 1(1.598,0.025) 2(-1.802,0.025)
  round 12 smd paste-15 mask+0.5: Touch(0,0)
  Keep-Out Layer lines w0.1: -1.252,0.975 1.048,0.975 1.048,-0.925 -1.252,-0.925 -1.252,0.975
  silkscreen extent -6.5,-6.5 6.5,6.5
TP [mm]
  round 1 hole 0.6: 1(2.827,-0.018)
  silkscreen extent -2.83,-2.84 2.85,2.84
"TSW SMD-3*6*5" [mm] "3*6*5mm"
  rect 2.5x1.5 smd: 1(-4.318,0) 2(4.318,0)
  silkscreen extent -3.21,-1.9 3.09,1.9, body extent -4.6,-1.75 4.6,1.75, height 5.1
USB-C/S_C [mm] "Type-C 6P母座"
  oval 1.2x2 hole 0.5 slot 1 at 90 deg: 0(-4.32,2.55) 0(4.32,2.55)
  oval 1.2x2 hole 0.5 slot 1.1 at 90 deg: 0(-4.32,6.25) 0(4.32,6.25)
  rect 0.7x2 smd: A5(-0.5,7.05) B5(0.5,7.05)
  rect 0.8x2 smd: A9(1.52,7.05) B9(-1.52,7.05)
  rect 0.9x2 smd: A12(2.75,7.05) B12(-2.75,7.05)
  silkscreen extent -4.57,-0.13 4.57,4.83, body extent -4.47,0 4.48,7.05, height 3.16

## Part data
5V GND/SHIELD: library part "Header 3", "3P接插件"
BEEP1: library part BEEP, "蜂鸣器"
BOOT KEY RST: library part "TSW DIP-2Pin-6x6", "2脚直插6x6轻触开关"
C1 C2 C4 C5 C6 C7 C9 C10 C12 C14 C16 C17 C18 C20 C21 C23 C25 C26: library part C, "无极性贴片电容"
DAC VCC_JUMP: library part "Header 2", "2P接插件"
DEBUG: library part ISP_5Pin, "程序下载端口"
E1 E2 E3: library part C-CM, "贴片电解电容"
F1: library part FU, "贴片保险丝"
K1 K2 K3 K4 K5 K6 K7 K8: library part TK
LD1 LD2 LD3 LD4 LD5 LD6 LD7 LD8 LD9 LD10 LD11 LD12 LD13 LD14 LD15 LD16 LD17 LD18 LD19 LD20 LD21 LD22 LD23 LD24 LD25 LD26 LD27 LD28 LD29 LD30 LD31 LD32 LD33 LD34: library part LED4020
LED1 LED2 LED3: library part LED-SMD, "贴片LED"
Q1 Q2: library part 8050-DIP, "高频放大-NPN型"
R1 R4: library part R
R2 R3 R5 R6 R7 R8 R9 R10 R11 R12 R13 R14 R15 R17 R18 R19 R20 R21 R22 R23 R24 R25 R26 R27 R30 R31 R32 R33 R34 R35 R36 R37 R38 R39 R40 R41 R42 R43 R44: library part R, "贴片电阻"
R16 R28 R29: library part Res, "Resistor"
RT1: library part RG5528, "光敏电阻"
USART: library part ISP_4Pin, "程序下载端口"
USB: library part USB-C_6P/S, "USB-C_6P型母接口"
V1: library part AMS1117, "三端稳压芯片"
VD1 VD2: library part DIODE
X1: library part XTAL-2P, "2脚无源脚晶振"

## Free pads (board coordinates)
  round 1.2 hole 0.7: 2(-85.177,-21.415) 3(-85.141,-30.531)

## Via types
v1: diameter 0.6, hole 0.4, Top Layer to Bottom Layer, 174 vias

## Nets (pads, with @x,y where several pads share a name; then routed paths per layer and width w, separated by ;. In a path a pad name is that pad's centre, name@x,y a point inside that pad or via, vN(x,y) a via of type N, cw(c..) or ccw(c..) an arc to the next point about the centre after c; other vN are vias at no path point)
backlight: R5.2 U1.11 | length 20.1
  Top Layer w0.2: v1(-66.637,-40.208) -65.85,-40.208 -65.469,-40.589 -65.469,-42.52 -66.078,-43.129 -66.078,-44.221 -65.52,-44.78 v1(-65.494,-44.78)
  Bottom Layer w0.2: R5.2@-70.219,-35.169 -67.079,-35.169 -66.637,-35.611 v1(-66.637,-40.208) ; v1(-65.494,-44.78) -65.291,-44.983 -65.291,-47.219 U1.11@-63.002,-49.508
beep: R36.2 U1.12 | length 50.1
  Top Layer w0.2: v1(-65.088,-43.358) -62.484,-43.358 v1(-61.722,-42.596)
  Bottom Layer w0.2: v1(-65.088,-43.358) -64.885,-43.561 -64.885,-46.918 U1.12@-62.648,-49.154 ; v1(-61.722,-42.596) -61.722,-40.742 -59.893,-38.913 -58.128,-38.913 -56.426,-37.211 -25.565,-37.211 R36.2@-25.489,-37.287
BOOT0: BOOT.1 U1.60 | length 95.9
  Top Layer w0.2: v1(-63.437,-55.575) -59.754,-51.892 -59.754,-28.372 -59.741,-28.359 -59.741,-6.82 -58.966,-6.045 -20.485,-6.045 -20.333,-5.893 -20.333,-2.794 BOOT.1@-20.587,-2.54
  Bottom Layer w0.2: U1.60@-65.123,-57.254 -63.444,-55.575 v1(-63.437,-55.575)
CMOD: C7.2 U1.14 | length 7.4
  Bottom Layer w0.2: C7.2@-63.716,-41.747 -63.716,-46.672 U1.14@-61.941,-48.447
COM0: LCD.1 U1.17 | length 9.6
  Bottom Layer w0.2: U1.17@-58.438,-47.74 -55.766,-45.068 LCD.1@-55.766,-39.284
COM1: LCD.2 U1.18 | length 10.8
  Bottom Layer w0.2: U1.18@-58.084,-48.094 -53.226,-43.235 LCD.2@-53.226,-39.284
COM2: LCD.3 U1.19 | length 12.1
  Bottom Layer w0.2: U1.19@-57.731,-48.447 -50.686,-41.403 LCD.3@-50.686,-39.284
COM3: LCD.4 U1.20 | length 13.3
  Bottom Layer w0.2: U1.20@-57.377,-48.801 -57.377,-48.76 -48.146,-39.529 LCD.4@-48.146,-39.284
COM4: LCD.5 U1.21 | length 15.5
  Bottom Layer w0.2: U1.21@-57.024,-49.154 -48.992,-41.123 -47.444,-41.123 LCD.5@-45.606,-39.284
COM5: LCD.6 U1.22 | length 17.8
  Bottom Layer w0.2: U1.22@-56.67,-49.508 -48.996,-41.834 -45.615,-41.834 LCD.6@-43.066,-39.284
COM6: LCD.7 U1.23 | length 20.2
  Bottom Layer w0.2: U1.23@-56.317,-49.862 -48.721,-42.266 -43.507,-42.266 LCD.7@-40.526,-39.284
COM7: LCD.8 U1.24 | length 22.8
  Bottom Layer w0.2: U1.24@-55.963,-50.215 -48.414,-42.666 -41.113,-42.666 -37.859,-39.411 LCD.8@-37.986,-39.284
DAC1_OUT: C26.2 DAC.2 U1.42 | length 50.6
  Top Layer w0.2: v1(-59.154,-54.448) -54.283,-54.448 -47.917,-48.082 -44.209,-48.082 -36.843,-40.716 v1(-30.544,-40.716)
  Bottom Layer w0.2: v1(-59.154,-54.448) -59.154,-56.184 U1.42@-56.317,-59.021 ; v1(-30.544,-40.716) -23.417,-40.716 C26.2@-22.568,-41.565 -22.532,-41.529 DAC.2@-20.308,-41.529
DCOM0: K1.2 K2.2 K3.2 K4.2 U1.1 | length 180.9
  Top Layer w0.2: v1(-74.676,-118.313) -67.107,-118.313 v1(-67.056,-118.262) ; v1(-71.577,-96.139) -69.771,-94.333 -69.771,-53.172 v1(-68.72,-52.121) ; v1(-65.354,-118.262) -65.329,-118.288 -53.569,-118.288 v1(-53.543,-118.313) -53.518,-118.288 -32.487,-118.288 v1(-32.461,-118.262) -11.379,-118.262 v1(-11.278,-118.364)
  Bottom Layer w0.2: K1.2@-74.435,-109.862 K1.2@-74.525,-109.772 -74.676,-109.923 v1(-74.676,-118.313) -80.721,-118.313 -82.258,-116.776 -82.258,-104.096 -74.301,-96.139 v1(-71.577,-96.139) ; v1(-68.72,-52.121) -68.491,-51.892 -67.688,-51.892 U1.1@-66.537,-53.044 ; v1(-67.056,-118.262) v1(-65.354,-118.262) ; v1(-53.543,-118.313) -53.525,-118.295 K2.2@-53.525,-109.772 ; K3.2@-32.525,-109.772 -32.607,-109.854 -32.461,-110 v1(-32.461,-118.262) ; K4.2@-11.525,-109.772 -11.278,-110.019 -11.278,-116.675 v1(-11.278,-118.364)
DCOM1: K5.2 K6.2 K7.2 K8.2 U1.2 | length 162.3
  Top Layer w0.2: v1(-72.111,-95.377) -70.219,-93.485 -70.219,-52.603 v1(-68.771,-51.156)
  Bottom Layer w0.2: v1(-72.111,-95.377) -74.105,-95.377 -82.868,-104.14 -82.868,-131.039 -81.203,-132.704 -74.725,-132.704 K5.2@-74.525,-132.904 -74.423,-132.802 K8.2@-11.525,-132.802 ; v1(-68.771,-51.156) -67.718,-51.156 U1.2@-66.184,-52.69
DSEG0: R30.1 R38.1 U1.64 | length 39.3
  Top Layer w0.2: v1(-68.771,-57.785) -69.371,-58.385 -69.371,-59.7 -68.745,-60.325 v1(-68.745,-69.672)
  Bottom Layer w0.2: R30.1@-70.828,-91.755 R38.1@-69.423,-91.755 -69.423,-70.35 v1(-68.745,-69.672) v1@-68.669,-69.596 ; v1(-68.771,-57.785) -68.694,-57.708 -68.406,-57.708 U1.64@-66.537,-55.839
DSEG1: R31.1 R39.1 U1.63 | length 39.1
  Top Layer w0.2: v1(-68.771,-58.78) -68.771,-59.614 -67.983,-60.401 v1(-67.983,-70.333)
  Bottom Layer w0.2: v1(-68.771,-58.78) U1.63@-66.184,-56.193 ; v1(-67.983,-70.333) -68.847,-71.196 -68.847,-90.925 R39.1@-68.017,-91.755 R31.1@-66.612,-91.755
DSEG2: R32.1 R40.1 U1.62 | length 61.3
  Top Layer w0.2: v1(-68.034,-59.309) -67.348,-59.995 -67.348,-75.514 -68.021,-76.187 -68.021,-91.211 -64.541,-94.691 -51.105,-94.691 -50.28,-93.866 v1(-50.28,-90.729)
  Bottom Layer w0.2: v1(-68.034,-59.309) -68.034,-58.751 U1.62@-65.83,-56.547 ; v1(-50.28,-90.729) R32.1@-50.28,-91.755 R40.1@-48.789,-91.755
DSEG3: R33.1 R41.1 U1.61 | length 63.6
  Top Layer w0.2: v1(-67.12,-59.258) -66.866,-59.512 -66.866,-75.842 -67.621,-76.597 -67.621,-82.29 -67.589,-82.321 -67.589,-90.856 -64.22,-94.225 -51.985,-94.225 -51.46,-93.701 -51.46,-90.453 -50.773,-89.765 -48.043,-89.765 v1(-47.257,-90.551)
  Bottom Layer w0.2: v1(-67.12,-59.258) -67.12,-58.543 U1.61@-65.476,-56.9 ; v1(-47.257,-90.551) -47.257,-91.713 R41.1@-47.299,-91.755 R33.1@-45.809,-91.755
GND: C1.1 C2.1 C4.1 C5.1 C6.1 C7.1 C9.1 C10.1 C12.1 C14.1 C16.1 C17.1 C18.1 C20.2 C21.1 C23.1 C25.1 C26.1 D1.2 DAC.1 DEBUG.3 E1.2 E2.2 E3.2 GND/SHIELD.3 KEY.1 LD1.4 LD2.4 LD3.4 LD4.4 LD5.4 LD6.4 LD7.4 LD8.4 LD9.4 LD10.4 LD11.4 LD12.4 LD13.4 LD14.4 LD15.4 LD16.4 LD17.4 LD18.4 LD19.4 LD20.4 LD21.4 LD22.4 LD23.4 LD24.4 LD25.4 LD26.4 LD27.4 LD28.4 LD29.4 LD30.4 LD31.4 LD32.4 LD33.4 LD34.4 LED2.2 Q1.2 Q2.2 R1.1 R4.1 R6.1 R37.1 R43.2 RST.1 U1.15 USART.4 USB.0 USB.A12 USB.B12 V1.1
  other v1: -85.716,-96.311 -76.915,-96.311 -10.282,-96.311 -59.552,-96.072 -0.852,-95.682 -50.902,-95.555 -74.377,-94.67 -30.397,-93.796 -24.111,-93.796 -36.683,-92.539 -17.825,-92.539 -84.458,-88.767 -42.97,-88.767 -11.359,-88.767 -5.253,-87.51 -50.546,-86.081 -47.37,-84.367 -84.458,-83.738 -7.767,-83.738 -0.852,-81.852 -84.467,-78.718 -50.513,-78.709 -0.852,-78.081 -4.928,-77.826 -85.716,-76.195 -84.458,-73.68 -68.114,-73.68 -59.942,-73.052 -51.77,-72.423 -2.738,-72.423 -84.458,-68.651 -52.654,-66.548 -2.738,-66.137 -59.942,-65.508 -84.458,-63.622 -47.999,-59.851 -65.862,-59.588 -4.953,-59.563 -0.852,-59.222 -84.458,-58.594 -59.314,-58.594 -50.513,-58.594 -52.399,-57.965 -68.114,-54.822 -50.513,-54.822 -47.37,-54.193 -8.396,-54.193 -84.458,-53.565 -62.457,-52.936 -70.629,-51.05 -60.595,-51.002 -13.843,-49.606 -42.341,-49.164 -84.458,-48.536 -30.397,-47.278 -21.597,-47.278 -36.145,-46.74 -8.396,-46.65 -19.082,-44.764 -31.026,-44.135 -24.74,-44.135 -84.458,-43.507 -6.51,-43.507 -79.429,-42.249 -5.253,-38.478 -9.653,-36.592 -65.151,-34.798 -10.82,-28.959 -73.143,-19.619 -34.169,-17.105 -19.082,-10.819 -6.51,-10.819 -58.903,-9.093 -70,-6.418 -66.229,-6.418
KEY1: KEY.2 R29.1 U1.3 | length 107
  Top Layer w0.2: v1(-69.406,-49.428) -61.913,-49.428 -60.465,-47.981 -60.465,-6.223 -59.703,-5.461 -23.051,-5.461 -22.619,-5.029 -22.619,-1.473 -22.187,-1.041 -18.24,-1.041 -18.123,-1.159 -18.123,-1.89 -17.473,-2.54 KEY.2@-17.412,-2.54 -17.387,-2.565 v1(-15.685,-2.565)
  Bottom Layer w0.2: v1(-69.406,-49.428) -68.738,-49.428 U1.3@-65.83,-52.336 ; v1(-15.685,-2.565) -14.862,-2.565 R29.1@-14.836,-2.54
LED1: LED3.2 U1.10 | length 67.6
  Top Layer w0.254: v1(-66.053,-46.253) -61.837,-46.253 -61.095,-45.512 -61.095,-5.202 -60.821,-4.928 -45.631,-4.928 -45.2,-4.496 LED3.2@-45.2,-3.429
  Bottom Layer w0.2: v1(-66.053,-46.253) -66.053,-47.164 U1.10@-63.355,-49.862
LED_MOSI: R35.1 U1.59 | length 19.4
  Top Layer w0.2: v1(-65.926,-68.656) -60.922,-63.652 -60.922,-57.76 v1(-62.573,-56.109)
  Bottom Layer w0.2: v1(-65.926,-68.656) -65.926,-69.86 R35.1@-65.901,-69.886 ; U1.59@-64.769,-57.607 -64.747,-57.607 -63.319,-56.18 -62.644,-56.18 v1(-62.573,-56.109)
NetBEEP1_2: BEEP1.2 R34.2 VD1.1 | length 9.5
  Bottom Layer w0.4: R34.2@-16.838,-37.846 -14.618,-37.846 ; BEEP1.2@-13.359,-41.25 -13.359,-39.105 -14.618,-37.846 ; VD1.1@-13.234,-35.103 -13.234,-36.462 -14.618,-37.846
NetBOOT_2: BOOT.2 R16.1 | length 2.3
  Top Layer w0.2: BOOT.2@-29.223,-2.54 -29.198,-2.515 v1(-27.623,-2.515)
  Bottom Layer w0.2: v1(-27.623,-2.515) -27.597,-2.54 R16.1@-26.901,-2.54
NetC2_2: 5V.2 C2.2 D1.1 E2.1 R3.2 RT1.1 VCC_JUMP.1 | length 59.1
  Top Layer w0.3: VCC_JUMP.1@-55.487,-2.159 -55.487,-1.168 -55.004,-0.686 -50.879,-0.686 R3.2@-50.295,-1.27
  Top Layer w0.6: VCC_JUMP.1@-55.745,-2.417 VCC_JUMP.1@-55.487,-2.159 ; v1(-55.55,-35.077) -55.55,-13.868 -54.204,-12.522 v1(-54.178,-12.522)
  Bottom Layer w0.6: 5V.2@-64.783,-2.159 -64.783,-1.346 -64.123,-0.686 -60.833,-0.686 -60.076,-1.443 -60.076,-2.078 C2.2@-59.995,-2.159 E2.1@-58.09,-2.159 VCC_JUMP.1@-55.487,-2.159 -55.487,-3.975 -57.404,-5.893 -57.404,-7.226 ; D1.1@-59.436,-7.264 -57.442,-7.264 -57.404,-7.226 ; RT1.1@-58.387,-35.611 -56.083,-35.611 v1(-55.55,-35.077) ; v1(-54.178,-12.522) -54.178,-11.786 -57.404,-8.56 -57.404,-7.226
NetC3_2: R7.2 | length 26.9
  Bottom Layer w0.2: R7.2@-48.384,-61.992 -46.901,-60.509 -46.901,-56.871 -39.51,-49.479 -28.766,-49.479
